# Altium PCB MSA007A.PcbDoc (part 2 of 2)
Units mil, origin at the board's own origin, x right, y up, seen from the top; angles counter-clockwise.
Board outline 3130 x 2560 mil, 4 copper layers (Top Layer, MidLayer1, MidLayer2, Bottom Layer), stack 92.8 mil thick; 128 components, 60 nets, 229 pads, 68 vias.
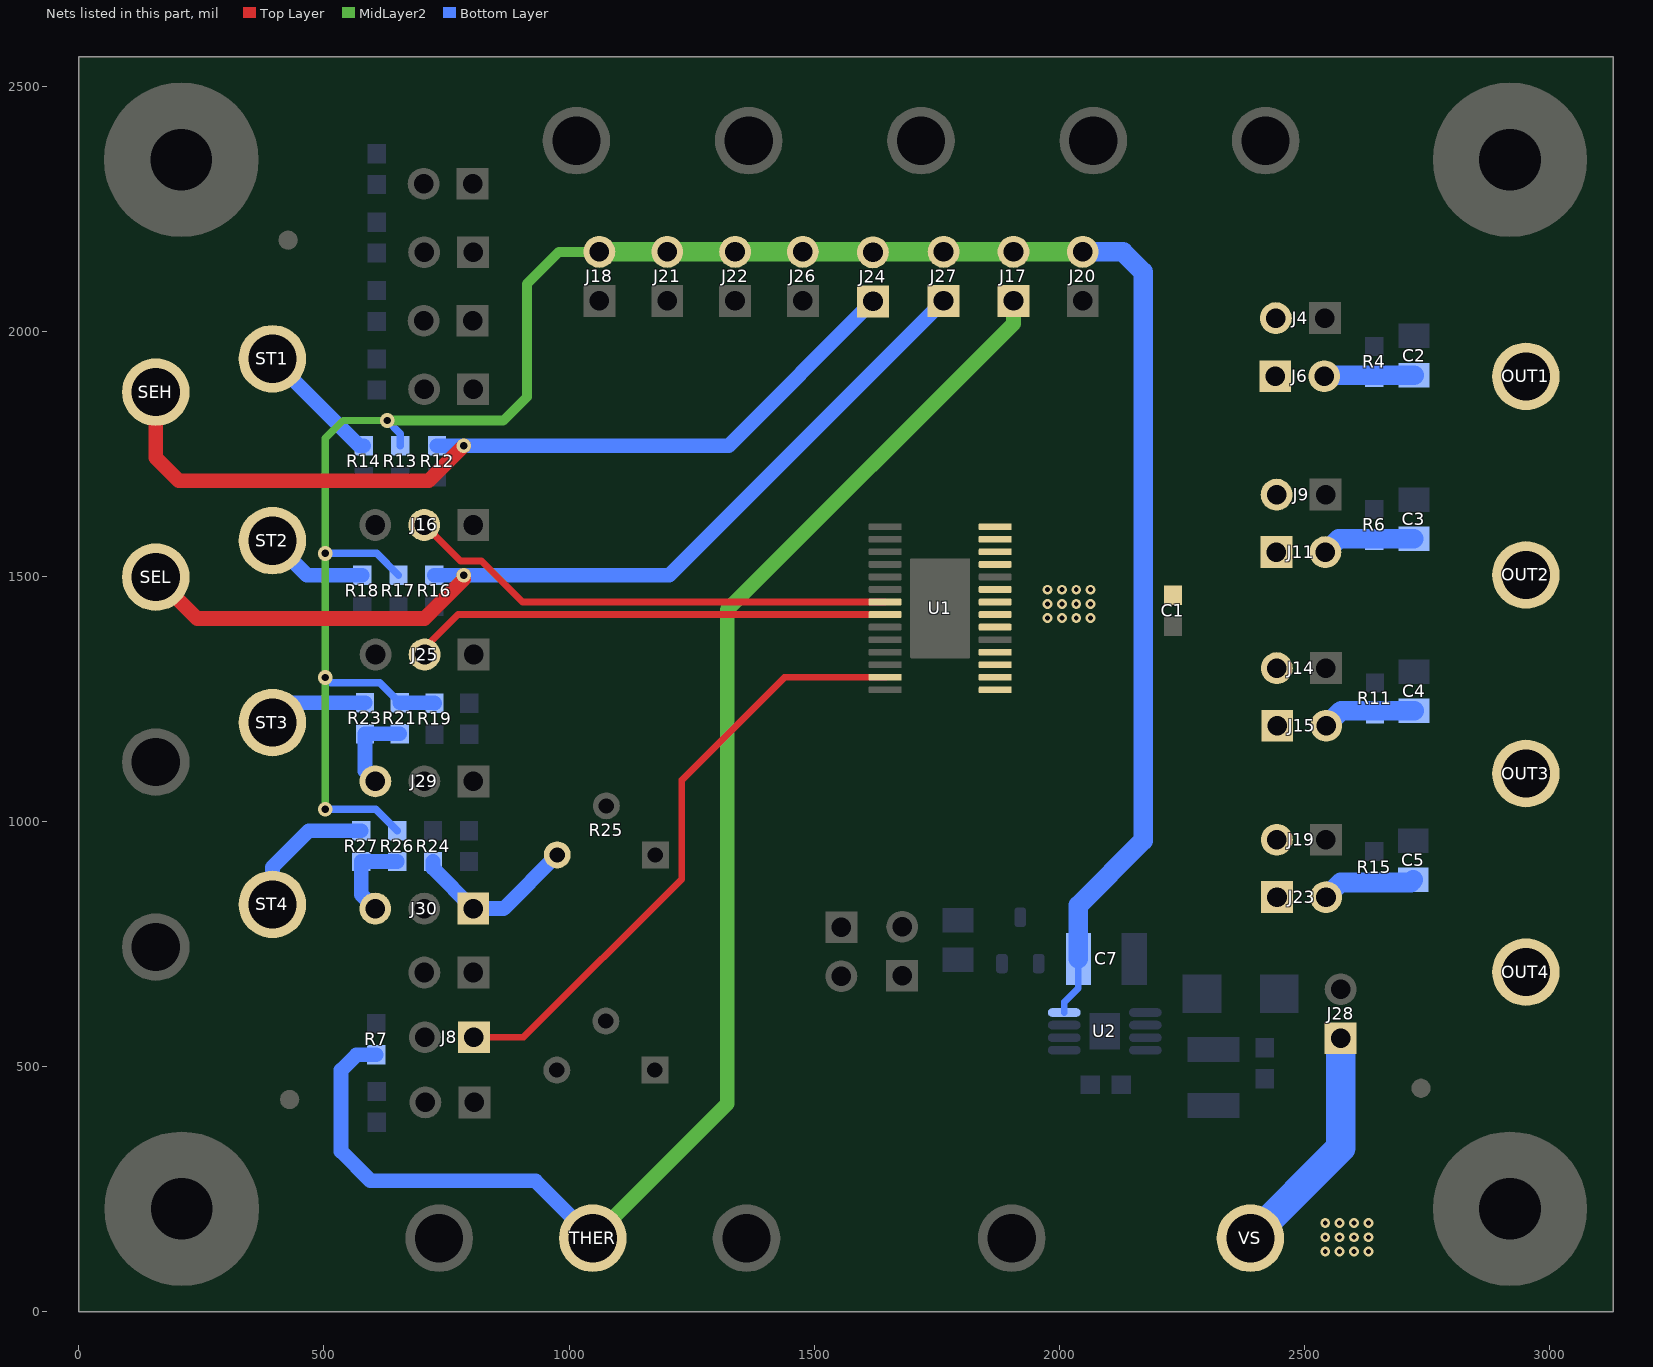
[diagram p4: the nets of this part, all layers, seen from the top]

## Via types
v1: diameter 20, hole 10, Top Layer to Bottom Layer, 36 vias
v2: diameter 15.75, hole 7.87, Top Layer to Bottom Layer, 18 vias
v3: diameter 30, hole 15, Top Layer to Bottom Layer, 9 vias
v4: diameter 19.68, hole 7.87, Top Layer to Bottom Layer, 5 vias

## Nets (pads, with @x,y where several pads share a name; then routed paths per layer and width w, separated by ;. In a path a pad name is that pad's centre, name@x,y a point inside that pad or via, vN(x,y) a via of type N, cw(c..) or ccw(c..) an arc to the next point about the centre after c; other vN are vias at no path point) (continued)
NetJ29_3: J29.3 R21.2 R23.2 | length 177
  Bottom Layer w30: J29.3@605,1082 583.7,1103.3 R23.2@583.7,1179.16 R21.2@654.7,1179.16
NetJ30_1: J30.1 R24.1 R25.3 | length 346.7
  Bottom Layer w30: R24.1@722.6,918.5 722.6,904.63 J30.1@804.73,822.5 866.5,822.5 R25.3@976,932
NetJ30_3: J30.3 R26.2 R27.2 | length 181.2
  Bottom Layer w30: J30.3@604.73,822.5 576,851.23 R27.2@576,918.5 R26.2@649.33,918.5
NetR14_1: R14.1 ST1.1 | length 259.5
  Bottom Layer w30: ST1.1@395,1944 572.5,1766.5 R14.1@581,1766.5
NetR18_1: R18.1 ST2.1 | length 212.2
  Bottom Layer w30: ST2.1@395,1573 465.5,1502.5 R18.1@578,1502.5
NetR23_1: R23.1 ST3.1 | length 205.3
  Bottom Layer w30: ST3.1@395,1202 435.15,1242.15 R23.1@583.7,1242.15
NetR27_1: R27.1 ST4.1 | length 287.9
  Bottom Layer w30: ST4.1@395,831 395,907 469.5,981.5 R27.1@576,981.5
OUT1: C2.1 J6.2 OUT1.1 R4.1 | length 184
  Bottom Layer w40: J6.2@2540.65,1908.3 2543.01,1910.65 C2.1@2723.7,1910.65
OUT1_IC: J6.1 U1.27 U1.28
OUT2: C3.1 J11.2 OUT2.1 R6.1 | length 191.6
  Bottom Layer w40: J11.2@2542.97,1549.68 2570.24,1576.95 C3.1@2723.32,1576.95
OUT2_IC: J11.1 U1.25 U1.26
OUT3: C4.1 J15.2 OUT3.1 R11.1 | length 191.9
  Bottom Layer w40: J15.2@2544.71,1195.48 2575.25,1226.02 C4.1@2724,1226.02
OUT3_IC: J15.1 U1.17 U1.18
OUT4: C5.1 J23.2 OUT4.1 R15.1 | length 192.7
  Bottom Layer w40: J23.2@2544.22,845.73 2574.21,875.73 R15.1@2642.27,875.73 2716.77,875.73 C5.1@2722.27,881.22
OUT4_IC: J23.1 U1.15 U1.16
SEH: J24.1 R12.2 SEH.1 | length 1822.4
  Top Layer w30: SEH.1@157,1876 157,1742 204,1695 713.56,1695 v3(785,1766.44)
  Bottom Layer w30: R12.2@730.68,1766.44 v3(785,1766.44) 1325.44,1766.44 J24.1@1620,2061
SEH/ST1_IC: J16.2 U1.7 | length 1005.2
  Top Layer w14: J16.2@704.68,1604.95 778.43,1531.2 821.6,1531.2 905,1447.8 U1.7@1644.8,1447.8
SEL: J27.1 R16.2 SEL.1 | length 1975
  Top Layer w30: SEL.1@157,1498.67 241.67,1414 705,1414 785,1494 v3(785,1502.2)
  Bottom Layer w30: R16.2@725.3,1502.2 v3(785,1502.2) 1204.2,1502.2 J27.1@1764,2062
SEL/ST2_IC: J25.2 U1.8 | length 981.2
  Top Layer w14: J25.2@705.3,1340.7 705.3,1354.3 773.2,1422.2 U1.8@1644.8,1422.2
THER: J17.1 R7.2 THER.1 | length 3105.3
  MidLayer2 w30: THER.1@1048.5,150 1323,424.5 1323,1432 1906.67,2015.67 J17.1@1906.67,2062
  Bottom Layer w30: R7.2@607,524.5 566.5,524.5 535,493 535,327 595,267 931.5,267 THER.1@1048.5,150
THER_IC: J8.1 U1.13 | length 1261.3
  Top Layer w14: J8.1@806,560 907,560 1230,883 1230,1085 1439.25,1294.25 U1.13@1644.8,1294.25
V_+5V: C7.1 J17.2 J18.2 J20.2 J21.2 J22.2 J24.2 J26.2 J27.2 R13.1 R17.1 R19.1 R21.1 R26.1 U2.8 | length 4950.9
  MidLayer2 w15: v3(503,1025) v3(503,1294) v3(503,1547) 503,1782 539,1818 v3(629,1818)
  MidLayer2 w20: v3(629,1818) 866,1818 914,1866 914,2097 979,2162 J18.2@1062,2162
  MidLayer2 w40: J18.2@1062,2162 J21.2@1200.33,2162 J22.2@1338.67,2162 J26.2@1477,2162 J27.2@1764,2162 J17.2@1906.67,2162 J20.2@2048,2162
  Bottom Layer w14: U2.8@2010.32,610.39 2010.32,632.09 2038.91,660.68 C7.1@2038.91,720
  Bottom Layer w15: v3(503,1025) 605.83,1025 R26.1@649.33,981.5 ; v3(503,1294) 514,1283 613.85,1283 R21.1@654.7,1242.15 ; v3(503,1547) 607.5,1547 R17.1@652,1502.5 ; v3(629,1818) 656,1791 R13.1@656,1766.5
  Bottom Layer w30: R21.1@654.7,1242.15 724.7,1242.15 R19.1@725.7,1241.15
  Bottom Layer w40: C7.1@2038.91,720 2038.91,828.91 2171,961 2171,2121 2130,2162 J20.2@2048,2162
VS: C1.2 J4.2 J9.2 J14.2 J19.2 J28.1 U1.20 U1.21 U1.22 U1.23 VS.1 | length 484.2
  Bottom Layer w60: VS.1@2390,150 2574,334 J28.1@2574,558
  other v1: 2542.67,123 2572,123 2601.33,123 2630.67,123 2542.67,152 2572,152 2601.33,152 2630.67,152 2542.67,181 2572,181 2601.33,181 2630.67,181 1976,1415 2005.33,1415 2034.67,1415 2064,1415 1976,1444 2005.33,1444 2034.67,1444 2064,1444 1976,1473 2005.33,1473 2034.67,1473 2064,1473
pads on no net: D1.2 FID1.1 FID2.1 FID3.1 H1.1 H2.1 H3.1 H4.1 R8.1 R25.1 SH-J1.0 SH-J2.0 SH-J3.0 SH-J4.0 SH-J5.0 SH-J6.0 SH-J7.0 SH-J8.0 SH-J9.0 SH-J10.0 SH-J11.0 SH-J12.0 SH-J13.0 SH-J14.0 SH-J15.0 SH-J16.0 SH-J17.0 SH-J18.0 SH-J19.0 U1.2 U1.19 U1.24 U2.3 U2.6 U2.7

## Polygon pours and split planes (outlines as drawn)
GND on Top Layer "Top Layer-No Net 10" (solid, remove dead copper, pour order 30): 40,2519 40,40 93,40 3090,40 3090,2520 40,2520 40,2519
VS on Top Layer "Top Layer-No Net 9" (solid, pour order 26): 1835,1389 2171,1389 2199,1361 2203,1357 2358,1357 2358,1268 2364,1262 2429,1262 2483,1262 2486,1265 2490,1269 2490,1373 2490,1483 2476,1497 2475,1498 1974,1498 1954,1498 1936,1480 1935,1479 1835,1479 1835,1389
GND_IC on Top Layer "Top Layer-No Net 8" (solid, pour order 25): 1695,1538 1695,1586 1695,1632 1672,1632 1608,1632 1608,1757 1905,1757 1905,1632 1818,1632 1818,1238 1905,1238 1905,1113 1607,1113 1607,1238 1695,1238 1695,1627.91 1695,1632
OUT4 on Top Layer "Top Layer-No Net 7" (solid, pour order 23): 2511,900 2823,900 2921,900 3021,800 3037,784 3037,609 2896,609 2708,797 2701,804 2512,804 2511,805 2511,900
OUT3 on Top Layer "Top Layer-No Net 6" (solid, pour order 22): 2515,1248 2512,1245 2512,1146 2801,1146 2807,1140 2927,1020 3040,1020 3040,1189 2981,1248 2515,1248
OUT1 on Top Layer "Top Layer-No Net 4" (solid, pour order 21): 2509,1938 2509,1859 2510,1858 2512,1856 2805,1856 2835,1856 2899,1792 3037,1792 3037,1993 3025,2005 3023,2007 2864,2007 2829,2007 2760,1938 2510,1938
OUT2 on Top Layer "Top Layer-No Net 5" (solid, pour order 20): 2507,1603 2507,1498 2786,1498 2852,1432 2885,1399 3059,1399 3059,1599 3061,1601 3060,1602 2507,1602
OUT1_IC on Top Layer "Top Layer-No Net" (solid, pour order 19): 1835,1609 1929,1609 1961,1641 2278.35,1958.35 2490.65,1958.35 2490.65,1858.3 2391,1858.3 2266.3,1858.3 1976,1568 1835,1568 1835,1609
OUT4_IC on Top Layer "Top Layer-No Net 3" (solid, pour order 18): 1834,1301 1834,1261 1835,1260 1936,1260 1941,1260 2407,794 2408.68,795.68 2494.22,795.68 2494.22,895.73 2494.17,895.79 2394.22,895.79 2384.21,895.79 2061,1219 1979,1301 1834,1301
OUT2_IC on Top Layer "Top Layer-No Net 1" (solid, pour order 17): 1834,1557 1834,1518 1835,1517 1903,1517 2492.97,1517 2492.97,1599.73 2345.73,1599.73 2305,1559 2303,1557 1834,1557
OUT3_IC on Top Layer "Top Layer-No Net 2" (solid, pour order 16): 1834,1312 2054,1312 2089,1312 2134,1312 2299,1147 2300.57,1145.43 2494.71,1145.43 2494.71,1245 2494.24,1245.48 2394.71,1245.48 2293.52,1245.48 2186,1353 2156,1353 1834,1353 1834,1312
GND on Bottom Layer "Top Layer-No Net 10" (solid, remove dead copper, pour order 29): 40,2519 40,40 93,40 3090,40 3090,2520 40,2520 40,2519
GND_IC on Bottom Layer "Top Layer-No Net 8" (solid, pour order 24): 1695,1538 1695,1586 1695,1632 1672,1632 1608,1632 1608,1757 1905,1757 1905,1632 1818,1632 1818,1238 1905,1238 1905,1113 1607,1113 1607,1238 1695,1238 1695,1627.91 1695,1632
GND on MidLayer1 "Top Layer-No Net 10" (solid, remove dead copper, pour order 28): 40,2519 40,40 93,40 3090,40 3090,2520 40,2520 40,2519
VS on MidLayer2 "Top Layer-No Net 10" (solid, remove dead copper, pour order 27): 40,2519 40,40 93,40 3090,40 3090,2520 40,2520 40,2519

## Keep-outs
Keep-Out Layer:
  lines w10: -5,0 ccw(c0,0) 0,-5 ; -5,0 ccw(c0,0) 0,-5 ; -5,0 ccw(c0,0) 0,-5 ; -5,0 ccw(c0,0) 0,-5 ; -5,0 ccw(c0,0) 0,-5 ; -5,0 ccw(c0,0) 0,-5
  lines w15: 0,0 3130,0 3130,2560 0,2560 0,0
  text ".Layer_Name" at 577,-858.49 h60

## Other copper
Top Layer:
  text ".Layer_Name" at 577,-858.49 h60
Bottom Layer:
  text ".Layer_Name" at 577,-858.49 h60

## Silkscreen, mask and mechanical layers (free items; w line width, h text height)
Top Overlay:
  text "IN1" at 1005,1915 h40
  text "IN2" at 1151,1915 h40
  text "IN3" at 1297,1915 h40
  text "IN4" at 1443,1915 h40
  text "SEH" at 1589,1915 h40
  text "SEL" at 1735,1915 h40
  text "DIAG_EN" at 2032,1915 h40
  text "THER" at 1857,1914 h40
  text "A" at 1763,1108 h30
  text "MSA007" at 1581,1105 h30
  text "TPS4H160EVM" at 1723,1027 h45
  text "LDO" at 2642,589 h40
  text ".Layer_Name" at 577,-858.49 h30
Bottom Overlay:
  text ".Layer_Name" at 577,-858.49 h60
Top Paste:
  text ".Layer_Name" at 577,-858.49 h60
Bottom Paste:
  text ".Layer_Name" at 577,-858.49 h60
Top Solder:
  text ".Layer_Name" at 577,-858.49 h60
  text ".Layer_Name" at 577,-858.49 h60
Bottom Solder:
  text ".Layer_Name" at 577,-858.49 h60
Drill Guide:
  text ".Layer_Name" at 577,-858.49 h60
M1 Board Outline:
  the board outline again, w15
  text ".Layer_Name" at 577,-858.49 h60
M2 Board Dimensions:
  rectangle: 125,-410.5 500,-285.5
  rectangle: 0,-285.5 125,-160.5
  lines w7: 0,-285.5 1000,-285.5 ; 125,-410.5 125,-160.5 ; 250,-410.5 250,-160.5 ; 500,-410.5 500,-160.5 ; 750,-410.5 750,-160.5 ; 0,-410.5 0,-160.5 1000,-160.5 1000,-410.5 0,-410.5
  text ".Layer_Name" at 577,-858.49 h60
M3 3D STEP Top:
  text ".Layer_Name" at 577,-858.49 h60
M4 3D STEP Bottom:
  text ".Layer_Name" at 577,-858.49 h60
M5 Assembly Top:
  lines w10: -292,-930.17 6308,-930.17 ; -292,-726.83 6310,-726.83 ; -292,-523.5 -292,-1133.5 3713,-1133.5 6310,-1133.5 6310,-523.5 -291.5,-523.5 -291.5,-1133.5 1284,-1133.5 ; 2173,-1133.5 2173,-523.5 ; 3440,-726.83 3440,-523.5 ; 4280,-726.83 4280,-523.5 ; 4902,-1140 4902,-937.17
  text "COMPONENTS MARKED 'DNP' SHOULD NOT BE POPULATED." at 1153.5,-318.5 h60
  text "ASSEMBLY VARIANT:" at 1153,-434 h60
  text ".VariantName" at 2189,-434 h60
  text "PCB VIEWED FROM TOP SIDE" at -228.5,-655.67 h60
  text "BOARD #:" at 2248,-655.67 h60
  text ".PRJ_Number" at 2793.5,-655.67 h60
  text "REV:" at 3638,-655.67 h60
  text ".PCB_Rev" at 3929.5,-655.67 h60
  text "SVN REV:" at 4476,-655.67 h60
  text ".VersionControl_RevNumber" at 4982,-655.67 h60
  text "IGNORE ->" at -228.5,-858.49 h60
  text "PLOT NAME =" at -228.5,-1064.34 h60
  text ".plot_File_Name" at 577,-1064.34 h60
  text "GENERATED    :" at 2250,-1064.34 h60
  text ".Print_Date" at 3119.5,-1064.34 h60
  text ".Print_Time" at 3848.5,-1064.34 h60
  text "TEXAS INSTRUMENTS" at 5113,-1064.34 h60
M6 Assembly Bottom:
  lines w10: -292.5,-727.33 6309.5,-727.33 ; -290.5,-930.67 6309.5,-930.67 ; 1115.5,-1140.5 1115.5,-937.67 ; 1737.5,-727.33 1737.5,-524 ; 2577.5,-727.33 2577.5,-524 ; 3844.5,-1134 3844.5,-524 ; 4733.5,-1134 6309,-1134 6309,-524 -292.5,-524 -292.5,-1134 2304.5,-1134 6309.5,-1134 6309.5,-524
  text "COMPONENTS MARKED 'DNP' SHOULD NOT BE POPULATED." at 6102,-318 h60
  text ".VariantName" at 5058,-434 h60
  text "ASSEMBLY VARIANT:" at 6097,-434 h60
  text ".VersionControl_RevNumber" at 1035.5,-656.17 h60
  text "SVN REV:" at 1541.5,-656.17 h60
  text ".PCB_Rev" at 2088,-656.17 h60
  text "REV:" at 2379.5,-656.17 h60
  text ".PRJ_Number" at 3224,-656.17 h60
  text "BOARD #:" at 3769.5,-656.17 h60
  text "PCB VIEWED FROM BOTTOM SIDE" at 6246,-656.17 h60
  text "IGNORE ->" at 2547.85,-858.49 h60
  text "TEXAS INSTRUMENTS" at 904.5,-1064.84 h60
  text ".Print_Time" at 2169,-1064.84 h60
  text ".Print_Date" at 2898,-1064.84 h60
  text "GENERATED    :" at 3767.5,-1064.84 h60
  text ".plot_File_Name" at 5440.5,-1064.84 h60
  text "PLOT NAME =" at 6246,-1064.84 h60
M9 Title Sheet:
  drawing of 57 lines, arcs and shapes, not listed
  text "1" at 739.84,8036.5 h70
  text "2" at 3235.5,8036.5 h70
  text "3" at 5724.84,8036.5 h70
  text "4" at 8231.51,8036.5 h70
  text "5" at 10730.5,8036.5 h70
  text "6" at 13235.5,8036.5 h70
  text "A" at -416.5,6893.5 h70
  text "A" at 14383.5,6893.5 h70
  text "B" at -416.5,4513.5 h70
  text "B" at 14383.5,4513.5 h70
  text "C" at -416.5,2138.5 h70
  text "C" at 14383.5,2138.5 h70
  text "PROJECT TITLE:" at 11343.5,277.5 h45
  text ".PRJ_Title" at 11393.5,144.17 h70
  text "DESIGNED FOR:" at 11343.5,-23.5 h45
  text ".PRJ_Customer" at 11393.5,-163.5 h70
  text "D" at -416.5,-231.5 h70
  text "D" at 14383.5,-231.5 h70
  text "FILE NAME:" at 11343.5,-323.5 h45
  text ".PCB_File_Name_No_Path" at 11393.5,-443.5 h70
  text "Texas Instruments (TI) and/or its licensors do not warrant the accuracy or completeness of this specification" at 6374,-605.34 h45
  text "ENGINEER:" at 11343.5,-613.5 h45
  text "LAYOUT BY:" at 12848.5,-613.5 h45
  text "or any information contained therein. TI and/or its licensors do not warrant that this design will meet" at 6329.01,-718 h45
  text ".PRJ_Engineer" at 11393.5,-768.49 h70
  text ".PCB_Layout" at 12899,-768.49 h70
  text "the specifications, will be suitable for your application or fit for any particular purpose, or will operate in" at 6329.01,-830.67 h45
  text ".Layer_Name" at 577,-858.49 h60
  text "ALTIUM DESIGNER VERSION:" at 12848.5,-923.5 h45
  text "an implementation. TI and/or its licensors do not warrant that the design is production worthy. You should" at 6329.01,-943.33 h45
  text "completely validate and test your design implementation to confirm the system functionality for your application." at 6374,-1056 h45
  text ".print_Scale" at 11393.5,-1056.83 h70
  text ".Application_BuildNumber" at 12899,-1056.83 h70
  text "1" at 739.84,-1263.5 h70
  text "2" at 3235.5,-1263.5 h70
  text "3" at 5724.84,-1263.5 h70
  text "4" at 8231.51,-1263.5 h70
  text "5" at 10730.5,-1263.5 h70
  text "6" at 13235.5,-1263.5 h70
M10 Fab Notes:
  drawing of 185 lines, arcs and shapes, not listed
  text "DESIGN INFORMATION" at 12381.02,5910 h60
  text "MIN. TRACK WIDTH:" at 11736.46,5730 h60
  text "8" at 12832.7,5730 h60
  text "MIL" at 12987.46,5730 h60
  text "MIN. CLEARANCE:" at 11736.46,5598 h60
  text "0.2" at 12772.7,5598 h60
  text "mm" at 12987.46,5598 h60
  text "MIN. VIA PAD SIZE:" at 11736.46,5466 h60
  text "24" at 12802.71,5466 h60
  text "MIL" at 12987.46,5466 h60
  text "0.05mm (2MIL)" at 12431.46,5324.29 h60
  text "MINIMUM ANNULAR RING" at 11407.23,5320 h60
  text "EXTERNAL" at 13139.46,5320 h60
  text "PER" at 11607.23,5202 h60
  text "IPC-D-275 CLASS 2 LEVEL C" at 11827.23,5202 h60
  text "MIL, HOLES" at 13315.46,5089.71 h60
  text "+/-" at 12923,5089 h60
  text "+/-" at 13777,5089 h60
  text "REGISTRATION TOLERANCES:" at 11407.23,5084 h60
  text "METAL" at 12607,5084 h60
  text "5" at 13183.2,5084 h60
  text "3" at 14016.2,5084 h60
  text "MIL" at 14132.46,5084 h60
  text "MATERIAL:" at 11332.46,4874.54 h60
  text "FR-4 High Tg" at 12318.9,4734.21 h60
  text "FR-408" at 11753.46,4725.64 h60
  text "X" at 12165.46,4725.64 h60
  text "OTHER" at 13241.46,4725.64 h60
  text "62 MIL (1.6mm) +/-10%" at 12073.56,4562.92 h60
  text "THICKNESS:" at 11407.23,4558.64 h60
  text "X" at 11945.4,4558.64 h60
  text "OTHER" at 13358.46,4558.64 h60
  text "TOLERANCE:" at 11407.23,4400.64 h60
  text "X" at 12246.53,4400.64 h60
  text "ANSI IPC-6012 TYPE 3 CLASS 2" at 12433.48,4400.64 h60
  text "OTHER +/-" at 12433.46,4244.64 h60
  text "BOW & TWIST:" at 11407.23,4087.64 h60
  text "X" at 12246.53,4087.64 h60
  text "ANSI IPC-6012 TYPE 3 CLASS 2" at 12433.48,4087.64 h60
  text "OTHER +/-" at 12433.46,3929.13 h60
  text "DRILLING:" at 11332.46,3790.64 h60
  text "REFERENCE:" at 11407.23,3673.64 h60
  text "X" at 12055.46,3673.64 h60
  text "AS SHOWN" at 12242.46,3673.64 h60
  text "X" at 12956.46,3673.64 h60
  text "NC_DRILL FILES" at 13093.46,3673.64 h60
  text "PTH MIN COPPER THICKNESS:" at 11407.23,3515.64 h60
  text "X" at 12757.46,3515.64 h60
  text "1MIL" at 12894.46,3515.64 h60
  text "OTHER" at 13391.46,3515.64 h60
  text "BOARD FINISH:" at 11332.46,3356.64 h60
  text "SILKSCREEN:" at 11487.68,3238.64 h60
  text "X" at 12436.46,3238.64 h60
  text "TOP" at 12562.46,3238.64 h60
  text "X" at 12946.46,3238.64 h60
  text "BOTTOM" at 13073.46,3238.64 h60
  text "SILKSCREEN COLOR:" at 11487.68,3071.64 h60
  text "X" at 12435.42,3071.64 h60
  text "WHITE" at 12562.46,3071.64 h60
  text "OTHER" at 13073.46,3071.64 h60
  text "SOLDER RESIST COLOR:" at 11487.68,2901.64 h60
  text "X" at 12055.42,2742.44 h60
  text "GREEN" at 12182.46,2742.44 h60
  text "BLUE" at 12773.46,2742.44 h60
  text "OTHER" at 13311.46,2742.44 h60
  text "IMMERSION GOLD (ENIG)" at 12393.46,2553.92 h60
  text "ENEPIG" at 13731,2550.64 h60
  text "SURFACE FINISH:" at 11332.46,2549.64 h60
  text "X" at 12206.51,2549.64 h60
  text "IMM. TIN/SILVER OR EQUIV" at 11662,2392.64 h60
  text "OTHER" at 13093.46,2392.64 h60
  text "ARRAY/PANEL:" at 11332.46,2213.64 h60
  text "CUT AND TRIM PER MECH LAYER 1" at 12393.46,2209.35 h60
  text "N.C. ROUTE" at 12393.46,2057.64 h60
  text "X" at 13072.46,2057.64 h60
  text "V. SCORE" at 13259.46,2057.64 h60
  text "CERTIFICATION:" at 11332.46,1920.64 h60
  text "MATERIALS AND WORKMANSHIP FOR ALL PCBS" at 12057.46,1920.64 h60
  text "TO MEET OR EXCEED THE REQUIREMENTS OF:" at 12057.46,1822.64 h60
  text "X" at 11683.96,1686.13 h60
  text "ANSI IPC-A-600F CLASS ->" at 11822.96,1686.13 h60
  text "X" at 13462.02,1686.13 h60
  text "2" at 13580.96,1686.14 h60
  text "1" at 13265.96,1684.64 h60
  text "3" at 13934.96,1684.64 h60
  text "X" at 11686.02,1526.64 h60
  text "UL 94V-0" at 11822.96,1526.64 h60
  text "X" at 12498.02,1526.64 h60
  text "RoHS" at 12634.96,1526.64 h60
  text "OTHER" at 13279.36,1526.64 h60
  text "PER ORDER" at 13676.42,1526.64 h60
  text "ADDITIONAL REQUIREMENTS:" at 11332.46,1385.64 h60
  text "MICROSECTION:" at 11407.23,1270.64 h60
  text "YES" at 12312.96,1270.64 h60
  text "REQUIRED" at 13174.46,1114.49 h60
  text "BARE BOARD ELEC. TEST:" at 11407.23,1111.64 h60
  text "NONE" at 12712.96,1111.64 h60
  text "X" at 13047.46,1111.64 h60
  text "PER ORDER" at 13766.46,1111.64 h60
  text "MANUFACTURER'S UL:" at 11407.23,954.64 h60
  text "RAIL" at 12572.96,950.35 h60
  text "METAL" at 13064.77,950.35 h60
  text "X" at 13440,950 h60
  text "SILK" at 13576.46,950.35 h60
  text ".Layer_Name" at 577,-858.49 h60
M11 Gerber Information:
  lines w10: -292,-930.17 6308,-930.17 ; -292,-726.83 6310,-726.83 ; -292,-523.5 -292,-1133.5 3713,-1133.5 6310,-1133.5 6310,-523.5 -291.5,-523.5 -291.5,-1133.5 1284,-1133.5 ; 2173,-1133.5 2173,-523.5 ; 3440,-726.83 3440,-523.5 ; 4280,-726.83 4280,-523.5 ; 4902,-1140 4902,-937.17
  text "ALL ARTWORK VIEWED FROM TOP SIDE" at -228.5,-655.67 h60
  text "BOARD #:" at 2248,-655.67 h60
  text ".PRJ_Number" at 2793.5,-655.67 h60
  text "REV:" at 3638,-655.67 h60
  text ".PCB_Rev" at 3929.5,-655.67 h60
  text "SVN REV:" at 4476,-655.67 h60
  text ".VersionControl_RevNumber" at 4982,-655.67 h60
  text "LAYER NAME =" at -228.5,-858.49 h60
  text "PLOT NAME =" at -228.5,-1064.34 h60
  text ".plot_File_Name" at 577,-1064.34 h60
  text "GENERATED    :" at 2250,-1064.34 h60
  text ".Print_Date" at 3119.5,-1064.34 h60
  text ".Print_Time" at 3848.5,-1064.34 h60
  text "TEXAS INSTRUMENTS" at 5113,-1064.34 h60
M12 Stackup:
  drawing of 295 lines, arcs and shapes, not listed
  text "Layer" at 6340,4023 h60
  text "Name" at 6749.91,4023 h60
  text "Material" at 7679.66,4023 h60
  text "Thickness" at 8539.42,4023 h60
  text "Constant" at 9189.26,4023 h60
  text "Board Layer Stack" at 9759.12,4023 h60
  text "1" at 6340,3903 h60
  text "Top Overlay" at 6749.91,3903 h60
  text "2" at 6340,3783 h60
  text "Top Solder" at 6749.91,3783 h60
  text "Solder Resist" at 7679.66,3783 h60
  text "0.40mil" at 8539.42,3783 h60
  text "3.5" at 9189.26,3783 h60
  text "3" at 6340,3663 h60
  text "Top Layer" at 6749.91,3663 h60
  text "Copper" at 7679.66,3663 h60
  text "2.80mil" at 8539.42,3663 h60
  text "4" at 6340,3543 h60
  text "Dielectric1" at 6749.91,3543 h60
  text "FR-4" at 7679.66,3543 h60
  text "59.20mil" at 8539.42,3543 h60
  text "4.8" at 9189.26,3543 h60
  text "5" at 6340,3423 h60
  text "MidLayer1" at 6749.91,3423 h60
  text "Copper" at 7679.66,3423 h60
  text "1.40mil" at 8539.42,3423 h60
  text "6" at 6340,3303 h60
  text "Dielectric2" at 6749.91,3303 h60
  text "FR-4" at 7679.66,3303 h60
  text "12.60mil" at 8539.42,3303 h60
  text "4.8" at 9189.26,3303 h60
  text "7" at 6340,3183 h60
  text "MidLayer2" at 6749.91,3183 h60
  text "Copper" at 7679.66,3183 h60
  text "1.40mil" at 8539.42,3183 h60
  text "8" at 6340,3063 h60
  text "Dielectric3" at 6749.91,3063 h60
  text "FR-4" at 7679.66,3063 h60
  text "12.60mil" at 8539.42,3063 h60
  text "4.8" at 9189.26,3063 h60
  text "9" at 6340,2943 h60
  text "Bottom Layer" at 6749.91,2943 h60
  text "Copper" at 7679.66,2943 h60
  text "2.80mil" at 8539.42,2943 h60
  text "10" at 6340,2823 h60
  text "Bottom Solder" at 6749.91,2823 h60
  text "Solder Resist" at 7679.66,2823 h60
  text "0.40mil" at 8539.42,2823 h60
  text "3.5" at 9189.26,2823 h60
  text "11" at 6340,2703 h60
  text "Bottom Overlay" at 6749.91,2703 h60
  text ".Layer_Name" at 577,-858.49 h60
M13 Component Bodies Top:
  text ".Layer_Name" at 577,-858.49 h60
M14 Component Bodies Bottom:
  text ".Layer_Name" at 577,-858.49 h60
M15 Courtyards Top:
  text ".Layer_Name" at 577,-858.49 h60
M16 Courtyards Bottom:
  text ".Layer_Name" at 577,-858.49 h60
Drill Drawing:
  circle w3.33: c6434.72,1883.4 r14.93
  circle w3.33: c6434.72,1883.4 r24.89
  lines w3.33: 6409.83,1273.68 6422.27,1273.68 6422.27,1261.24 6447.16,1261.24 6447.16,1273.68 6459.6,1273.68 6459.6,1298.57 6447.16,1298.57 6447.16,1311.01 6422.27,1311.01 6422.27,1298.57 6409.83,1298.57 6409.83,1273.68 ; 6409.83,1410.56 6434.72,1423 6459.6,1410.56 6447.16,1435.44 6459.6,1460.33 6434.72,1447.89 6409.83,1460.33 6422.27,1435.44 6409.83,1410.56 ; 6409.83,1572.32 6422.27,1572.32 6434.72,1559.88 6447.16,1572.32 6459.6,1572.32 6447.16,1584.76 6459.6,1597.21 6447.16,1597.21 6434.72,1609.65 6422.27,1597.21 6409.83,1597.21 6422.27,1584.76 6409.83,1572.32 ; 6409.83,1758.97 6459.6,1758.97 6434.72,1709.2 6409.83,1758.97 ; 6409.83,2007.84 6459.6,2007.84 6459.6,2057.61 6409.83,2057.61 6409.83,2007.84 ; 6409.83,2182.04 6434.72,2157.16 6459.6,2182.04 6434.72,2206.93 6409.83,2182.04 ; 6419.78,1278.66 6427.25,1278.66 6427.25,1271.19 6442.18,1271.19 6442.18,1278.66 6449.65,1278.66 6449.65,1293.59 6442.18,1293.59 6442.18,1301.05 6427.25,1301.05 6427.25,1293.59 6419.78,1293.59 6419.78,1278.66 ; 6419.78,1420.51 6434.72,1427.98 6449.65,1420.51 6442.18,1435.44 6449.65,1450.37 6434.72,1442.91 6419.78,1450.37 6427.25,1435.44 6419.78,1420.51 ; 6419.78,1577.3 6427.25,1577.3 6434.72,1569.83 6442.18,1577.3 6449.65,1577.3 6442.18,1584.76 6449.65,1592.23 6442.18,1592.23 6434.72,1599.69 6427.25,1592.23 6419.78,1592.23 6427.25,1584.76 6419.78,1577.3 ; 6419.78,1749.01 6449.65,1749.01 6434.72,1719.15 6419.78,1749.01 ; 6419.78,2017.79 6449.65,2017.79 6449.65,2047.65 6419.78,2047.65 6419.78,2017.79
  lines w12: 6342,1216.44 9417.05,1216.44 ; 6342,2261.68 9417.05,2261.68 ; 6712.36,1067.12 6712.36,2411 ; 7069.36,1067.12 7069.36,2411 ; 7730.93,1067.12 7730.93,2411 ; 8015.07,1067.12 8015.07,2411 ; 8415.22,1067.12 8415.22,2411 ; 8972.36,1067.12 8972.36,2411 ; 6342,1067.12 9417.05,1067.12 9417.05,2411 6342,2411 6342,1067.12
  text "Symbol" at 6431.59,2306.48 h72
  text "Quantity" at 6757.16,2306.48 h72
  text "Finished Hole Size" at 7114.16,2306.48 h72
  text "Plated" at 7775.72,2306.48 h72
  text "Hole Type" at 8059.86,2306.48 h72
  text "Drill Layer Pair" at 8460.02,2306.48 h72
  text "Tolerance" at 9017.15,2306.48 h72
  text "23" at 6757.16,2157.16 h60
  text "7.87mil (0.200mm)" at 7114.16,2157.16 h60
  text "PTH" at 7775.72,2157.16 h60
  text "Round" at 8059.86,2157.16 h60
  text "0.00mil (0.000mm)" at 8460.02,2157.16 h60
  text "36" at 6757.16,2007.84 h60
  text "10.00mil (0.254mm)" at 7114.16,2007.84 h60
  text "PTH" at 7775.72,2007.84 h60
  text "Round" at 8059.86,2007.84 h60
  text "0.00mil (0.000mm)" at 8460.02,2007.84 h60
  text "9" at 6757.16,1858.52 h60
  text "15.00mil (0.381mm)" at 7114.16,1858.52 h60
  text "PTH" at 7775.72,1858.52 h60
  text "Round" at 8059.86,1858.52 h60
  text "0.00mil (0.000mm)" at 8460.02,1858.52 h60
  text "6" at 6757.16,1709.2 h60
  text "31.00mil (0.787mm)" at 7114.16,1709.2 h60
  text "PTH" at 7775.72,1709.2 h60
  text "Round" at 8059.86,1709.2 h60
  text "0.00mil (0.000mm)" at 8460.02,1709.2 h60
  text "64" at 6757.16,1559.88 h60
  text "40.00mil (1.016mm)" at 7114.16,1559.88 h60
  text "PTH" at 7775.72,1559.88 h60
  text "Round" at 8059.86,1559.88 h60
  text "0.00mil (0.000mm)" at 8460.02,1559.88 h60
  text "22" at 6757.16,1410.56 h60
  text "98.43mil (2.500mm)" at 7114.16,1410.56 h60
  text "PTH" at 7775.72,1410.56 h60
  text "Round" at 8059.86,1410.56 h60
  text "0.00mil (0.000mm)" at 8460.02,1410.56 h60
  text "4" at 6757.16,1261.24 h60
  text "125.98mil (3.200mm)" at 7114.16,1261.24 h60
  text "PTH" at 7775.72,1261.24 h60
  text "Round" at 8059.86,1261.24 h60
  text "0.00mil (0.000mm)" at 8460.02,1261.24 h60
  text "164 Total" at 6757.16,1111.92 h60
  text ".Layer_Name" at 577,-858.49 h60

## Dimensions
0,-410.5 to 1000,-410.5 on M2 Board Dimensions
0,0 to 3130,0 on M2 Board Dimensions
0,0 to 0,2560 on M2 Board Dimensions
